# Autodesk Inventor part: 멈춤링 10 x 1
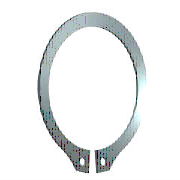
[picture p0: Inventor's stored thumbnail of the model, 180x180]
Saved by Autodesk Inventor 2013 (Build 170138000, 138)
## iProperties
IsCustomPart: 0
Created: 2015-11
Part Number: 멈춤링 10 x 1
Material: 스테인리스강
Description: 리테이닝 링(C형)
Document SubType Name: Modeling
Standard: KS B 1336
Designer: mdu
Standards Organization: KS
Language: ko-KR
Size Designation: 10 x 1
Categories: <MemberInstance><Categories><Category DisplayName="샤프트 부품" InternalName="7f7aeb1f-a693-4053-b835-cee3144e0d98" Mnemonic="SHFT"><Category DisplayName="써클립" Inter
Density: 8.08 g/cm^3
Mass: 0.434931 g
Surface Area: 1.9243 cm^2
Volume: 0.0538281 cm^3
Author: mdu
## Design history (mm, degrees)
sketch "스케치1"
  geometry: L1 (-6, 0)-(6, 0) reference; L2 (0, 20.189)-(0, -80.536) reference; L3 (-48.09, 0)-(48.09, 0) reference; L4 (-0.3, -9.791)-(-0.3, -12.791); L5 (-0.3, -6.54)-(-0.3, -13.29); L6 (-2.795, 1.6)-(3.672, 1.6); L7 (0.3, -6.54)-(0.3, -13.29); L8 (0.3, -9.791)-(0.3, -12.791); C1 r 0.6 at (-1.2, -11.486); C2 r 0.6 at (1.2, -11.486); A1 r 4.8 centre (0, -5) between (0.3, -9.791) and (-0.3, -9.791); A2 r 6.2 centre (0, -4.6) between (2.988, -10.033) and (-2.988, -10.033); A3 r 7.796 centre (0, -5) between (-1.418, -12.666) and (-0.3, -12.791); A4 r 1.2 centre (-1.2, -11.486) between (-2.383, -11.285) and (-1.418, -12.666); A5 r 1.2 centre (-3.566, -11.084) between (-2.383, -11.285) and (-2.988, -10.033); A6 r 1.2 centre (3.566, -11.084) between (2.988, -10.033) and (2.383, -11.285); A7 r 1.2 centre (1.2, -11.486) between (1.418, -12.666) and (2.383, -11.285); A8 r 7.796 centre (0, -5) between (0.3, -12.791) and (1.418, -12.666)
  constraints: 16 point on circle, 12 end point, 10 centre point, 9 symmetric about line, 5 point on line, 4 tangent, 3 coincident, 2 horizontal, 1 perpendicular, 1 vertical, 5 other
  dimensions: "d0" = 9.6 diameter of A1 (= ND); "d1" = 3 distance of L4.end L4.start (= SRB2); "d6" = 0.3 distance between parallel lines of L2 L5 (= 0.25 x SD5); "d7" = 1.6 distance between parallel lines of L6 L3 (= SRB1); "d8" = 0.4 distance of A1.centre A2.centre (= 0.25 x SRB1); "d9" = 1.2 radius of A4 (= SD5); "d10" = 1.2 radius of A5 (= SD5); "d11" = 0.9 distance from line of L4 A4.centre (= 0.75 x SD5); "d12" = 1.2 diameter of C1 (= SD5); "d13" = 1.2 diameter of C2 (= SD5); "d14" = 5 distance from line of A1.centre L1 (= 0.5 x WD)
extrude "본체" new body sketch "스케치1" distance "d2" = 1 (= SD); taper "d3" = 0 deg
workaxis "Work Axis1"
workplane "Work Plane1"
body "Solid1"
other parameters: "SD" = 1 [user parameter; used in 1 equation term], "SRB1" = 1.6 [user parameter; used in 2 equation terms], "ND" = 9.6 [user parameter; used in 1 equation term], "SRB2" = 3 [user parameter; used in 1 equation term], "SD5" = 1.2 [user parameter; used in 6 equation terms], "d15" = 0, "d16" = 0, "d17" = 0, "d41" = 0, "d42" = 0, "SD3" = 9.3 [user parameter], "WDMAX" = 11 [user parameter]
